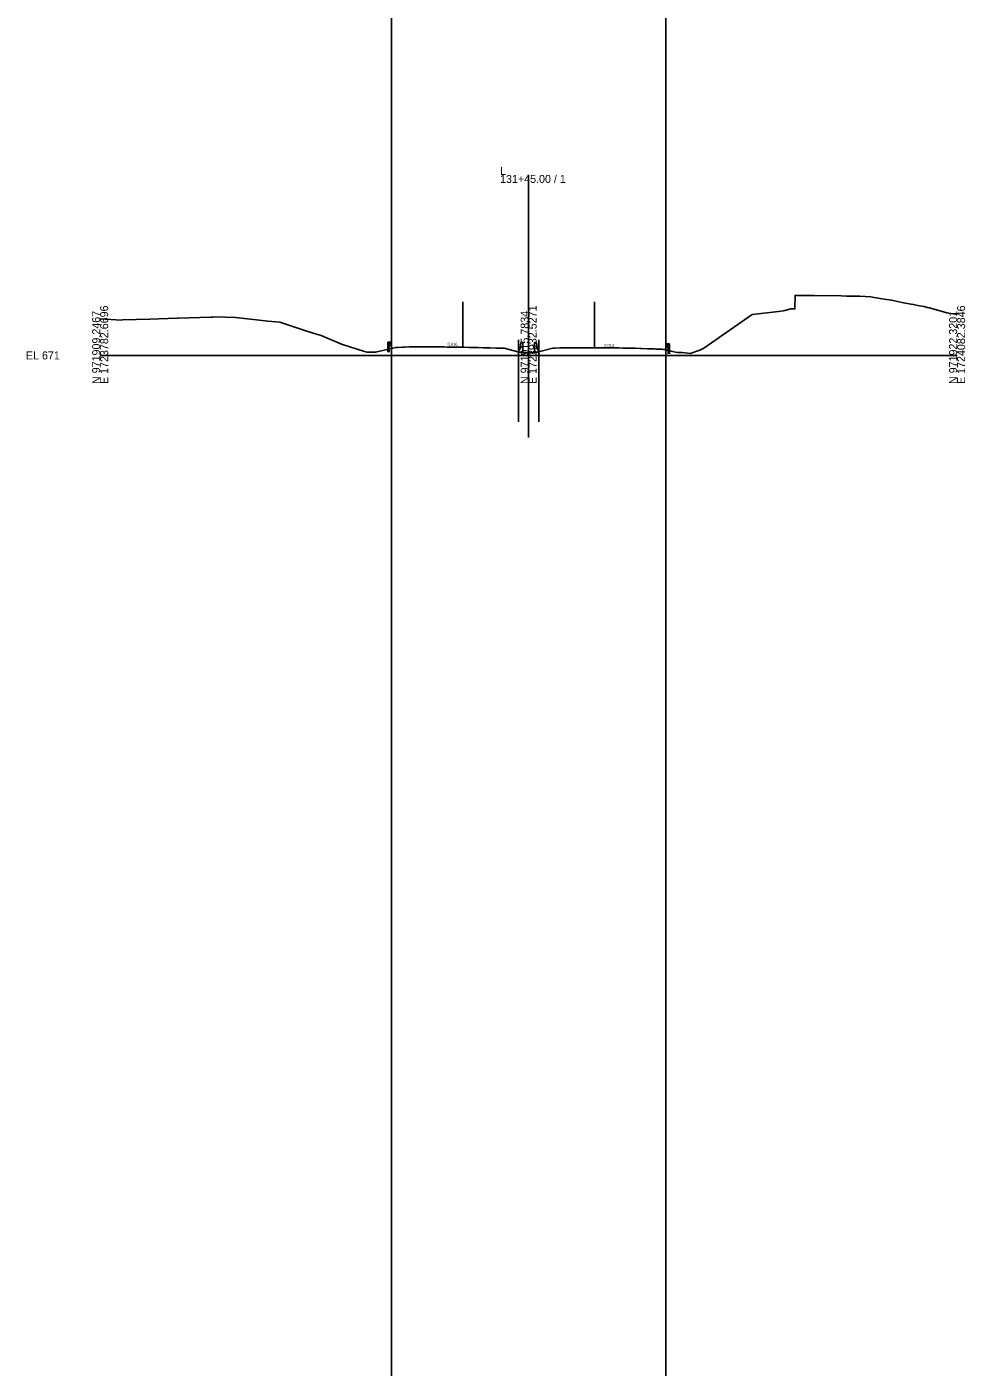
# Model space of a CAD drawing. Extents: x -26 to 303, y -29 to 15026.
# Drawn here: x -25.7 to 302.8, y 3646 to 4115 of the extents above; entities that cross this region are included whole.
import ezdxf

# ---------------------------------------------------------------- set-up
doc = ezdxf.new("R2010")
doc.units = 0
for name, color, linetype in [('Exist Cross Section Cell', 7, 'Continuous'), ('Exist XS Center Line Elevation Label', 7, 'Continuous'), ('Exist XS Ground Line', 7, 'Continuous'), ('Prop XS Ditch Standard Text', 7, 'Continuous'), ('Scratch_Level_0', 7, 'Continuous'), ('Typical Guardrail CELL', 7, 'Continuous'), ('Typical Median Barrier CELL', 7, 'Continuous')]:
    doc.layers.add(name, color=color, linetype=linetype)

msp = doc.modelspace()

# ---------------------------------------------------------------- linework, layer by layer
at = {"layer": 'Exist Cross Section Cell'}
for p, q in [((150, 4000), (150, 4063.16)), ((0, 4000), (150, 4000)), ((150, 4000), (300, 4000))]:
    msp.add_line(p, q, dxfattribs=at)
at = {"layer": 'Exist XS Ground Line'}
msp.add_lwpolyline([(0, 4012.77), (7.35, 4012.4), (7.77, 4012.41), (17.36, 4012.68), (26.95, 4012.99), (27.34, 4013.02), (38.79, 4013.4), (39.44, 4013.4), (40.36, 4013.46), (47.39, 4013.23), (55.72, 4012.38), (58.71, 4012), (62.87, 4011.69), (71.65, 4008.77), (74.9, 4007.65), (77.41, 4006.93), (84.49, 4003.98), (87.42, 4003.01), (92.54, 4001.41), (93.43, 4001.14), (93.81, 4001.13), (96.36, 4001.16), (102.45, 4002.57), (103.47, 4002.8), (104.18, 4002.83), (105.83, 4002.9), (106.52, 4002.92), (108.2, 4002.97), (109.03, 4002.99), (110.32, 4003), (111.21, 4003.01), (112.17, 4003.01), (114.05, 4003), (115.42, 4003.01), (116.54, 4003.01), (117.77, 4003), (119.05, 4003), (120.38, 4002.98), (121.53, 4002.96), (122.42, 4002.96), (123.04, 4002.96), (123.51, 4002.96), (124.03, 4002.95), (125.61, 4002.91), (126.53, 4002.88), (127.38, 4002.87), (129.04, 4002.83), (129.79, 4002.82), (131.54, 4002.78), (132.18, 4002.76), (134.07, 4002.7), (134.58, 4002.69), (135.76, 4002.65), (136.55, 4002.62), (138.72, 4002.58), (139.06, 4002.57), (141.03, 4002.51), (141.4, 4002.51), (146.26, 4001.32), (147.25, 4001.07), (147.95, 4000.96), (149.48, 4000.93), (150, 4000.82), (150.58, 4000.89), (152.03, 4000.95), (152.83, 4001.15), (153.89, 4001.4), (158.42, 4002.57), (159.17, 4002.59), (160.93, 4002.62), (161.56, 4002.63), (162.24, 4002.65), (164.49, 4002.7), (165.78, 4002.7), (166.61, 4002.7), (167.52, 4002.7), (169.1, 4002.71), (170.56, 4002.71), (171.59, 4002.71), (172.73, 4002.71), (174.1, 4002.71), (175.37, 4002.71), (176.62, 4002.71), (177.28, 4002.7), (177.78, 4002.69), (179.1, 4002.67), (180.14, 4002.65), (181.59, 4002.62), (183.15, 4002.59), (184.08, 4002.57), (185.81, 4002.53), (186.59, 4002.51), (187.3, 4002.5), (189.09, 4002.46), (189.47, 4002.45), (191.57, 4002.37), (192.1, 4002.35), (194.11, 4002.27), (194.56, 4002.25), (196.78, 4002.16), (197.26, 4002.14), (197.88, 4002.13), (198.01, 4001.98), (199.73, 4001.45), (201.98, 4001.09), (203.71, 4001.09), (206.56, 4000.68), (209.99, 4001.91), (211.33, 4002.51), (216.76, 4006.31), (228.29, 4014.28), (237.51, 4015.41), (239.13, 4015.61), (239.71, 4015.78), (241.8, 4016.26), (241.9, 4016.31), (243.21, 4016.29), (243.31, 4021.05), (243.92, 4021.03), (244.72, 4021.03), (246.33, 4021.03), (247.41, 4021.03), (248.95, 4021.01), (249.44, 4021.01), (249.95, 4021), (255.48, 4020.87), (256.08, 4021.02), (259.47, 4020.82), (261.24, 4020.78), (265.16, 4020.76), (265.84, 4020.75), (269.85, 4020.49), (271.02, 4020.26), (274.41, 4019.73), (277.06, 4019.37), (281.23, 4018.45), (284.67, 4017.85), (286.82, 4017.39), (288.47, 4017.08), (289.55, 4016.77), (290.3, 4016.66), (296.44, 4014.86), (300, 4014.28)], dxfattribs=at)
at = {"layer": 'Scratch_Level_0'}
for p, q in [((102, 15009.56), (102, -28.7)), ((198, 15009.56), (198, -28.7)), ((127, 4018.8), (127, 4002.87)), ((173, 4018.8), (173, 4002.71)), ((146.46, 4005.5), (146.46, 3976.8)), ((153.54, 4005.5), (153.54, 3976.8)), ((127, 4002.87), (120.38, 4002.98)), ((173, 4002.71), (185.81, 4002.53)), ((150, 4000), (150, 3971.3)), ((150, 4000), (150, 3971.3))]:
    msp.add_line(p, q, dxfattribs=at)
at = {"layer": 'Typical Guardrail CELL'}
for p, q in [((101.18, 4004.64), (100.68, 4004.64)), ((100.68, 4004.64), (100.68, 4002.16)), ((101.18, 4002.16), (100.68, 4002.16)), ((100.68, 4002.16), (100.68, 4001.15)), ((101.18, 4004.64), (101.18, 4002.16)), ((101.18, 4004.64), (101.68, 4004.64)), ((101.18, 4003.48), (101.68, 4003.48)), ((101.18, 4002.16), (101.18, 4001.15)), ((101.68, 4004.64), (101.68, 4003.48)), ((101.68, 4004.64), (101.97, 4004.44)), ((101.68, 4004.11), (101.97, 4004.31)), ((101.68, 4004.06), (101.68, 4004.11)), ((101.68, 4004.06), (101.68, 4004.02)), ((101.68, 4004.02), (101.97, 4003.82)), ((101.68, 4003.48), (101.97, 4003.69)), ((198.32, 4004.06), (198.03, 4003.86)), ((198.32, 4003.53), (198.03, 4003.73)), ((198.32, 4003.43), (198.03, 4003.23)), ((198.32, 4002.9), (198.03, 4003.1)), ((198.82, 4004.06), (198.32, 4004.06)), ((198.32, 4004.06), (198.32, 4002.9)), ((198.32, 4003.48), (198.32, 4003.53)), ((198.32, 4003.48), (198.32, 4003.43)), ((198.82, 4002.9), (198.32, 4002.9)), ((198.82, 4004.06), (198.82, 4001.57)), ((198.82, 4004.06), (199.32, 4004.06)), ((198.82, 4001.57), (199.32, 4001.57)), ((198.82, 4001.57), (198.82, 4000.56)), ((199.32, 4004.06), (199.32, 4001.57)), ((199.32, 4001.57), (199.32, 4000.56))]:
    msp.add_line(p, q, dxfattribs=at)
for centre, start, end in [((101.92, 4004.38), 304.9888, 54.997), ((101.92, 4003.75), 304.9634, 54.9941), ((198.08, 4003.79), 125.003, 235.0112), ((198.08, 4003.17), 125.0059, 235.0366)]:
    msp.add_arc(centre, 0.0776, start, end, dxfattribs=at)
at = {"layer": 'Typical Median Barrier CELL'}
for p, q in [((146.46, 4001.51), (146.92, 4002.17)), ((146.46, 4001.1), (146.46, 4001.51)), ((147.96, 4001.1), (146.46, 4001.1)), ((147.07, 4002.56), (147.29, 4004.51)), ((147.29, 4004.51), (147.96, 4004.51)), ((147.96, 4004.51), (147.96, 4001.1)), ((152.71, 4004.51), (152.04, 4004.51)), ((152.04, 4004.51), (152.04, 4001.1)), ((152.04, 4001.1), (153.54, 4001.1)), ((152.93, 4002.56), (152.71, 4004.51)), ((153.54, 4001.51), (153.08, 4002.17)), ((153.54, 4001.1), (153.54, 4001.51))]:
    msp.add_line(p, q, dxfattribs=at)
for centre, start, end in [((146.24, 4002.65), 325.0039, 353.9447), ((153.76, 4002.65), 186.0553, 214.9961)]:
    msp.add_arc(centre, 0.833, start, end, dxfattribs=at)

# ---------------------------------------------------------------- texts
at = {"layer": 'Exist Cross Section Cell'}
for s, p in [('L', (140, 4063.16)), ('131+45.00 / 1', (140, 4060.36)), ('EL 671', (-26, 3998.6))]:
    msp.add_text(s, height=2.8, dxfattribs=at).set_placement(p)
for s, p in [('N 971909.2467', (0, 3990)), ('E 1723782.6696', (2.8, 3990)), ('N 971915.7834', (150, 3990)), ('E 1723932.5271', (152.8, 3990)), ('N 971922.3201', (300, 3990)), ('E 1724082.3846', (302.8, 3990))]:
    msp.add_text(s, height=2.8, rotation=90, dxfattribs=at).set_placement(p)
at = {"layer": 'Exist XS Center Line Elevation Label'}
msp.add_text('671.82', height=0.18, dxfattribs=at).set_placement((149.64, 4000.33))
at = {"layer": 'Prop XS Ditch Standard Text'}
for s, rotation, p in [('0.016', 359.0949, (121.62, 4003.48)), ('0.014', 359.182, (176.45, 4003.04))]:
    msp.add_text(s, height=1, rotation=rotation, dxfattribs=at).set_placement(p)

doc.saveas('drawing.dxf')
